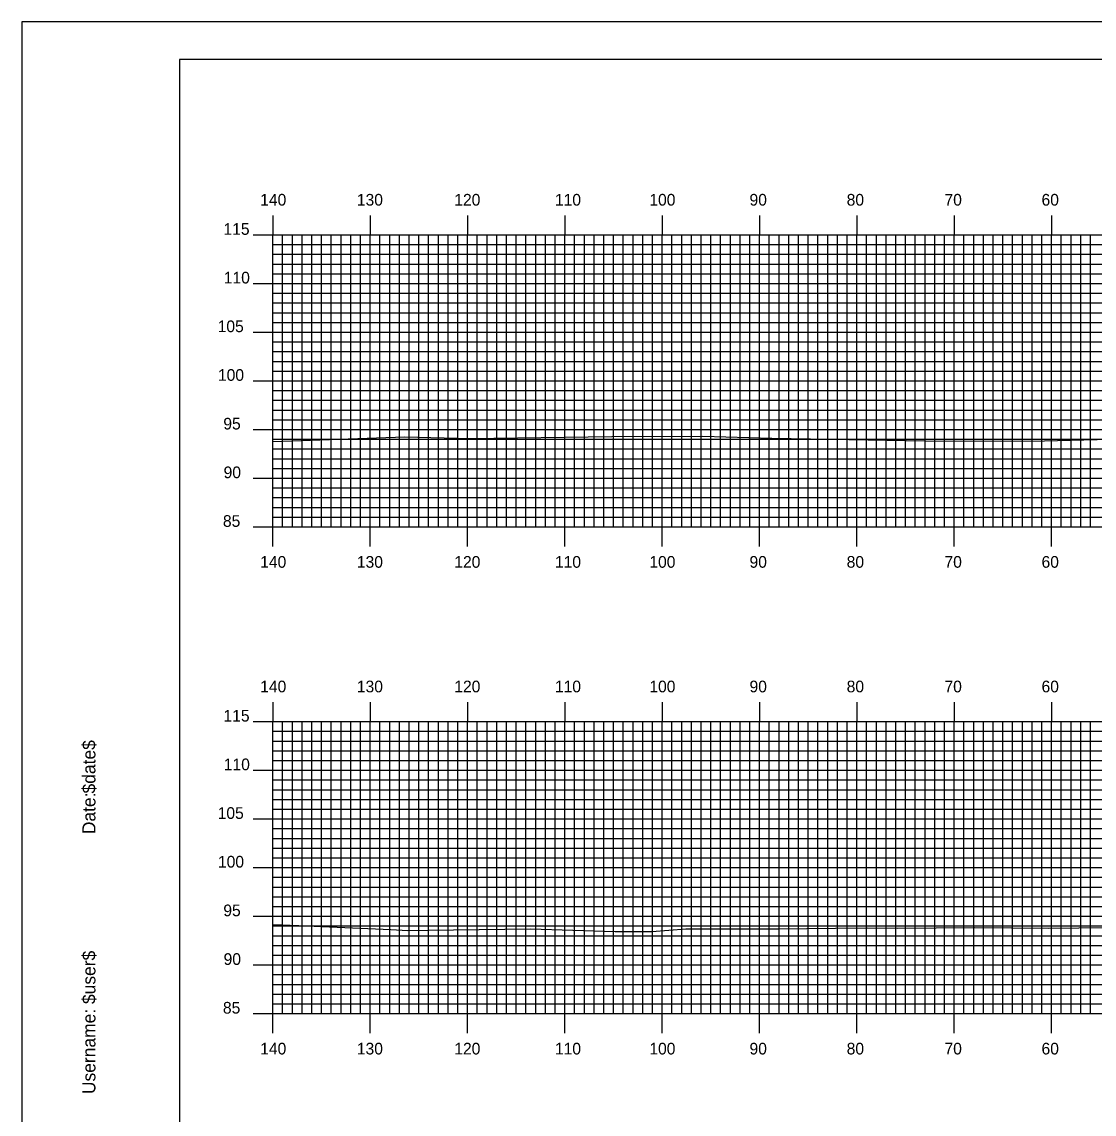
# Model space of a CAD drawing. Extents: x 1761004 to 1761347, y 442591 to 442811.
# Drawn here: x 1761003.9 to 1761114.1, y 442698.3 to 442810.5 of the extents above; entities that cross this region are included whole.
import ezdxf

# ---------------------------------------------------------------- set-up
doc = ezdxf.new("R2010")
doc.units = 0
for name, color, linetype in [('BORDER', 7, 'Continuous'), ('H_V ANNOTATION', 7, 'Continuous'), ('MAJOR', 7, 'Continuous'), ('MINOR', 7, 'Continuous'), ('PLOT BOUNDARY', 7, 'Continuous'), ('S_Roadway_Centerline', 7, 'Continuous')]:
    doc.layers.add(name, color=color, linetype=linetype)

msp = doc.modelspace()

# ---------------------------------------------------------------- linework, layer by layer
at = {"layer": 'BORDER'}
msp.add_lwpolyline([(1761020.13, 442596.67), (1761340.13, 442596.67), (1761340.13, 442806.67), (1761020.13, 442806.67)], close=True, dxfattribs=at)
at = {"layer": 'MAJOR'}
for p, q in [((1761029.73, 442790.67), (1761029.73, 442788.67)), ((1761039.73, 442790.67), (1761039.73, 442788.67)), ((1761049.73, 442790.67), (1761049.73, 442788.67)), ((1761059.73, 442790.67), (1761059.73, 442788.67)), ((1761069.73, 442790.67), (1761069.73, 442788.67)), ((1761079.73, 442790.67), (1761079.73, 442788.67)), ((1761089.73, 442790.67), (1761089.73, 442788.67)), ((1761099.73, 442790.67), (1761099.73, 442788.67)), ((1761109.73, 442790.67), (1761109.73, 442788.67)), ((1761027.72, 442788.67), (1761029.73, 442788.67)), ((1761029.73, 442788.67), (1761309.73, 442788.67)), ((1761029.73, 442758.67), (1761029.73, 442788.67)), ((1761029.73, 442758.67), (1761029.73, 442788.67)), ((1761029.73, 442788.67), (1761309.73, 442788.67)), ((1761039.73, 442758.67), (1761039.73, 442788.67)), ((1761049.73, 442758.67), (1761049.73, 442788.67)), ((1761059.73, 442758.67), (1761059.73, 442788.67)), ((1761069.73, 442758.67), (1761069.73, 442788.67)), ((1761079.73, 442758.67), (1761079.73, 442788.67)), ((1761089.73, 442758.67), (1761089.73, 442788.67)), ((1761099.73, 442758.67), (1761099.73, 442788.67)), ((1761109.73, 442758.67), (1761109.73, 442788.67)), ((1761027.72, 442783.67), (1761029.73, 442783.67)), ((1761029.73, 442783.67), (1761309.73, 442783.67)), ((1761027.72, 442778.67), (1761029.73, 442778.67)), ((1761029.73, 442778.67), (1761309.73, 442778.67)), ((1761027.72, 442773.67), (1761029.73, 442773.67)), ((1761029.73, 442773.67), (1761309.73, 442773.67)), ((1761027.72, 442768.67), (1761029.73, 442768.67)), ((1761029.73, 442768.67), (1761309.73, 442768.67)), ((1761027.72, 442763.67), (1761029.73, 442763.67)), ((1761029.73, 442763.67), (1761309.73, 442763.67)), ((1761027.72, 442758.67), (1761029.73, 442758.67)), ((1761029.73, 442758.67), (1761309.73, 442758.67)), ((1761029.73, 442758.67), (1761309.73, 442758.67)), ((1761029.73, 442756.66), (1761029.73, 442758.67)), ((1761039.73, 442756.66), (1761039.73, 442758.67)), ((1761049.73, 442756.66), (1761049.73, 442758.67)), ((1761059.73, 442756.66), (1761059.73, 442758.67)), ((1761069.73, 442756.66), (1761069.73, 442758.67)), ((1761079.73, 442756.66), (1761079.73, 442758.67)), ((1761089.73, 442756.66), (1761089.73, 442758.67)), ((1761099.73, 442756.66), (1761099.73, 442758.67)), ((1761109.73, 442756.66), (1761109.73, 442758.67)), ((1761029.73, 442740.67), (1761029.73, 442738.67)), ((1761039.73, 442740.67), (1761039.73, 442738.67)), ((1761049.73, 442740.67), (1761049.73, 442738.67)), ((1761059.73, 442740.67), (1761059.73, 442738.67)), ((1761069.73, 442740.67), (1761069.73, 442738.67)), ((1761079.73, 442740.67), (1761079.73, 442738.67)), ((1761089.73, 442740.67), (1761089.73, 442738.67)), ((1761099.73, 442740.67), (1761099.73, 442738.67)), ((1761109.73, 442740.67), (1761109.73, 442738.67)), ((1761027.72, 442738.67), (1761029.73, 442738.67)), ((1761029.73, 442738.67), (1761309.73, 442738.67)), ((1761029.73, 442708.67), (1761029.73, 442738.67)), ((1761029.73, 442708.67), (1761029.73, 442738.67)), ((1761029.73, 442738.67), (1761309.73, 442738.67)), ((1761039.73, 442708.67), (1761039.73, 442738.67)), ((1761049.73, 442708.67), (1761049.73, 442738.67)), ((1761059.73, 442708.67), (1761059.73, 442738.67)), ((1761069.73, 442708.67), (1761069.73, 442738.67)), ((1761079.73, 442708.67), (1761079.73, 442738.67)), ((1761089.73, 442708.67), (1761089.73, 442738.67)), ((1761099.73, 442708.67), (1761099.73, 442738.67)), ((1761109.73, 442708.67), (1761109.73, 442738.67)), ((1761027.72, 442733.67), (1761029.73, 442733.67)), ((1761029.73, 442733.67), (1761309.73, 442733.67)), ((1761027.72, 442728.67), (1761029.73, 442728.67)), ((1761029.73, 442728.67), (1761309.73, 442728.67)), ((1761027.72, 442723.67), (1761029.73, 442723.67)), ((1761029.73, 442723.67), (1761309.73, 442723.67)), ((1761027.72, 442718.67), (1761029.73, 442718.67)), ((1761029.73, 442718.67), (1761309.73, 442718.67)), ((1761027.72, 442713.67), (1761029.73, 442713.67)), ((1761029.73, 442713.67), (1761309.73, 442713.67)), ((1761027.72, 442708.67), (1761029.73, 442708.67)), ((1761029.73, 442708.67), (1761309.73, 442708.67)), ((1761029.73, 442708.67), (1761309.73, 442708.67)), ((1761029.73, 442706.66), (1761029.73, 442708.67)), ((1761039.73, 442706.66), (1761039.73, 442708.67)), ((1761049.73, 442706.66), (1761049.73, 442708.67)), ((1761059.73, 442706.66), (1761059.73, 442708.67)), ((1761069.73, 442706.66), (1761069.73, 442708.67)), ((1761079.73, 442706.66), (1761079.73, 442708.67)), ((1761089.73, 442706.66), (1761089.73, 442708.67)), ((1761099.73, 442706.66), (1761099.73, 442708.67)), ((1761109.73, 442706.66), (1761109.73, 442708.67))]:
    msp.add_line(p, q, dxfattribs=at)
at = {"layer": 'MINOR'}
for p, q in [((1761030.73, 442758.67), (1761030.73, 442788.67)), ((1761031.73, 442758.67), (1761031.73, 442788.67)), ((1761032.73, 442758.67), (1761032.73, 442788.67)), ((1761033.73, 442758.67), (1761033.73, 442788.67)), ((1761034.73, 442758.67), (1761034.73, 442788.67)), ((1761035.73, 442758.67), (1761035.73, 442788.67)), ((1761036.73, 442758.67), (1761036.73, 442788.67)), ((1761037.73, 442758.67), (1761037.73, 442788.67)), ((1761038.73, 442758.67), (1761038.73, 442788.67)), ((1761040.73, 442758.67), (1761040.73, 442788.67)), ((1761041.73, 442758.67), (1761041.73, 442788.67)), ((1761042.73, 442758.67), (1761042.73, 442788.67)), ((1761043.73, 442758.67), (1761043.73, 442788.67)), ((1761044.73, 442758.67), (1761044.73, 442788.67)), ((1761045.73, 442758.67), (1761045.73, 442788.67)), ((1761046.73, 442758.67), (1761046.73, 442788.67)), ((1761047.73, 442758.67), (1761047.73, 442788.67)), ((1761048.73, 442758.67), (1761048.73, 442788.67)), ((1761050.73, 442758.67), (1761050.73, 442788.67)), ((1761051.73, 442758.67), (1761051.73, 442788.67)), ((1761052.73, 442758.67), (1761052.73, 442788.67)), ((1761053.73, 442758.67), (1761053.73, 442788.67)), ((1761054.73, 442758.67), (1761054.73, 442788.67)), ((1761055.73, 442758.67), (1761055.73, 442788.67)), ((1761056.73, 442758.67), (1761056.73, 442788.67)), ((1761057.73, 442758.67), (1761057.73, 442788.67)), ((1761058.73, 442758.67), (1761058.73, 442788.67)), ((1761060.73, 442758.67), (1761060.73, 442788.67)), ((1761061.73, 442758.67), (1761061.73, 442788.67)), ((1761062.73, 442758.67), (1761062.73, 442788.67)), ((1761063.73, 442758.67), (1761063.73, 442788.67)), ((1761064.73, 442758.67), (1761064.73, 442788.67)), ((1761065.73, 442758.67), (1761065.73, 442788.67)), ((1761066.73, 442758.67), (1761066.73, 442788.67)), ((1761067.73, 442758.67), (1761067.73, 442788.67)), ((1761068.73, 442758.67), (1761068.73, 442788.67)), ((1761070.73, 442758.67), (1761070.73, 442788.67)), ((1761071.73, 442758.67), (1761071.73, 442788.67)), ((1761072.73, 442758.67), (1761072.73, 442788.67)), ((1761073.73, 442758.67), (1761073.73, 442788.67)), ((1761074.73, 442758.67), (1761074.73, 442788.67)), ((1761075.73, 442758.67), (1761075.73, 442788.67)), ((1761076.73, 442758.67), (1761076.73, 442788.67)), ((1761077.73, 442758.67), (1761077.73, 442788.67)), ((1761078.73, 442758.67), (1761078.73, 442788.67)), ((1761080.73, 442758.67), (1761080.73, 442788.67)), ((1761081.73, 442758.67), (1761081.73, 442788.67)), ((1761082.73, 442758.67), (1761082.73, 442788.67)), ((1761083.73, 442758.67), (1761083.73, 442788.67)), ((1761084.73, 442758.67), (1761084.73, 442788.67)), ((1761085.73, 442758.67), (1761085.73, 442788.67)), ((1761086.73, 442758.67), (1761086.73, 442788.67)), ((1761087.73, 442758.67), (1761087.73, 442788.67)), ((1761088.73, 442758.67), (1761088.73, 442788.67)), ((1761090.73, 442758.67), (1761090.73, 442788.67)), ((1761091.73, 442758.67), (1761091.73, 442788.67)), ((1761092.73, 442758.67), (1761092.73, 442788.67)), ((1761093.73, 442758.67), (1761093.73, 442788.67)), ((1761094.73, 442758.67), (1761094.73, 442788.67)), ((1761095.73, 442758.67), (1761095.73, 442788.67)), ((1761096.73, 442758.67), (1761096.73, 442788.67)), ((1761097.73, 442758.67), (1761097.73, 442788.67)), ((1761098.73, 442758.67), (1761098.73, 442788.67)), ((1761100.73, 442758.67), (1761100.73, 442788.67)), ((1761101.73, 442758.67), (1761101.73, 442788.67)), ((1761102.73, 442758.67), (1761102.73, 442788.67)), ((1761103.73, 442758.67), (1761103.73, 442788.67)), ((1761104.73, 442758.67), (1761104.73, 442788.67)), ((1761105.73, 442758.67), (1761105.73, 442788.67)), ((1761106.73, 442758.67), (1761106.73, 442788.67)), ((1761107.73, 442758.67), (1761107.73, 442788.67)), ((1761108.73, 442758.67), (1761108.73, 442788.67)), ((1761110.73, 442758.67), (1761110.73, 442788.67)), ((1761111.73, 442758.67), (1761111.73, 442788.67)), ((1761112.73, 442758.67), (1761112.73, 442788.67)), ((1761113.73, 442758.67), (1761113.73, 442788.67)), ((1761029.73, 442787.67), (1761309.73, 442787.67)), ((1761029.73, 442787.67), (1761031.73, 442787.67)), ((1761029.73, 442786.67), (1761309.73, 442786.67)), ((1761029.73, 442786.67), (1761031.73, 442786.67)), ((1761029.73, 442785.67), (1761309.73, 442785.67)), ((1761029.73, 442785.67), (1761031.73, 442785.67)), ((1761029.73, 442784.67), (1761309.73, 442784.67)), ((1761029.73, 442784.67), (1761031.73, 442784.67)), ((1761029.73, 442782.67), (1761309.73, 442782.67)), ((1761029.73, 442782.67), (1761031.73, 442782.67)), ((1761029.73, 442781.67), (1761309.73, 442781.67)), ((1761029.73, 442781.67), (1761031.73, 442781.67)), ((1761029.73, 442780.67), (1761309.73, 442780.67)), ((1761029.73, 442780.67), (1761031.73, 442780.67)), ((1761029.73, 442779.67), (1761309.73, 442779.67)), ((1761029.73, 442779.67), (1761031.73, 442779.67)), ((1761029.73, 442777.67), (1761309.73, 442777.67)), ((1761029.73, 442777.67), (1761031.73, 442777.67)), ((1761029.73, 442776.67), (1761309.73, 442776.67)), ((1761029.73, 442776.67), (1761031.73, 442776.67)), ((1761029.73, 442775.67), (1761309.73, 442775.67)), ((1761029.73, 442775.67), (1761031.73, 442775.67)), ((1761029.73, 442774.67), (1761309.73, 442774.67)), ((1761029.73, 442774.67), (1761031.73, 442774.67)), ((1761029.73, 442772.67), (1761309.73, 442772.67)), ((1761029.73, 442772.67), (1761031.73, 442772.67)), ((1761029.73, 442771.67), (1761309.73, 442771.67)), ((1761029.73, 442771.67), (1761031.73, 442771.67)), ((1761029.73, 442770.67), (1761309.73, 442770.67)), ((1761029.73, 442770.67), (1761031.73, 442770.67)), ((1761029.73, 442769.67), (1761309.73, 442769.67)), ((1761029.73, 442769.67), (1761031.73, 442769.67)), ((1761029.73, 442767.67), (1761309.73, 442767.67)), ((1761029.73, 442767.67), (1761031.73, 442767.67)), ((1761029.73, 442766.67), (1761309.73, 442766.67)), ((1761029.73, 442766.67), (1761031.73, 442766.67)), ((1761029.73, 442765.67), (1761309.73, 442765.67)), ((1761029.73, 442765.67), (1761031.73, 442765.67)), ((1761029.73, 442764.67), (1761309.73, 442764.67)), ((1761029.73, 442764.67), (1761031.73, 442764.67)), ((1761029.73, 442762.67), (1761309.73, 442762.67)), ((1761029.73, 442762.67), (1761031.73, 442762.67)), ((1761029.73, 442761.67), (1761309.73, 442761.67)), ((1761029.73, 442761.67), (1761031.73, 442761.67)), ((1761029.73, 442760.67), (1761309.73, 442760.67)), ((1761029.73, 442760.67), (1761031.73, 442760.67)), ((1761029.73, 442759.67), (1761309.73, 442759.67)), ((1761029.73, 442759.67), (1761031.73, 442759.67)), ((1761030.73, 442708.67), (1761030.73, 442738.67)), ((1761031.73, 442708.67), (1761031.73, 442738.67)), ((1761032.73, 442708.67), (1761032.73, 442738.67)), ((1761033.73, 442708.67), (1761033.73, 442738.67)), ((1761034.73, 442708.67), (1761034.73, 442738.67)), ((1761035.73, 442708.67), (1761035.73, 442738.67)), ((1761036.73, 442708.67), (1761036.73, 442738.67)), ((1761037.73, 442708.67), (1761037.73, 442738.67)), ((1761038.73, 442708.67), (1761038.73, 442738.67)), ((1761040.73, 442708.67), (1761040.73, 442738.67)), ((1761041.73, 442708.67), (1761041.73, 442738.67)), ((1761042.73, 442708.67), (1761042.73, 442738.67)), ((1761043.73, 442708.67), (1761043.73, 442738.67)), ((1761044.73, 442708.67), (1761044.73, 442738.67)), ((1761045.73, 442708.67), (1761045.73, 442738.67)), ((1761046.73, 442708.67), (1761046.73, 442738.67)), ((1761047.73, 442708.67), (1761047.73, 442738.67)), ((1761048.73, 442708.67), (1761048.73, 442738.67)), ((1761050.73, 442708.67), (1761050.73, 442738.67)), ((1761051.73, 442708.67), (1761051.73, 442738.67)), ((1761052.73, 442708.67), (1761052.73, 442738.67)), ((1761053.73, 442708.67), (1761053.73, 442738.67)), ((1761054.73, 442708.67), (1761054.73, 442738.67)), ((1761055.73, 442708.67), (1761055.73, 442738.67)), ((1761056.73, 442708.67), (1761056.73, 442738.67)), ((1761057.73, 442708.67), (1761057.73, 442738.67)), ((1761058.73, 442708.67), (1761058.73, 442738.67)), ((1761060.73, 442708.67), (1761060.73, 442738.67)), ((1761061.73, 442708.67), (1761061.73, 442738.67)), ((1761062.73, 442708.67), (1761062.73, 442738.67)), ((1761063.73, 442708.67), (1761063.73, 442738.67)), ((1761064.73, 442708.67), (1761064.73, 442738.67)), ((1761065.73, 442708.67), (1761065.73, 442738.67)), ((1761066.73, 442708.67), (1761066.73, 442738.67)), ((1761067.73, 442708.67), (1761067.73, 442738.67)), ((1761068.73, 442708.67), (1761068.73, 442738.67)), ((1761070.73, 442708.67), (1761070.73, 442738.67)), ((1761071.73, 442708.67), (1761071.73, 442738.67)), ((1761072.73, 442708.67), (1761072.73, 442738.67)), ((1761073.73, 442708.67), (1761073.73, 442738.67)), ((1761074.73, 442708.67), (1761074.73, 442738.67)), ((1761075.73, 442708.67), (1761075.73, 442738.67)), ((1761076.73, 442708.67), (1761076.73, 442738.67)), ((1761077.73, 442708.67), (1761077.73, 442738.67)), ((1761078.73, 442708.67), (1761078.73, 442738.67)), ((1761080.73, 442708.67), (1761080.73, 442738.67)), ((1761081.73, 442708.67), (1761081.73, 442738.67)), ((1761082.73, 442708.67), (1761082.73, 442738.67)), ((1761083.73, 442708.67), (1761083.73, 442738.67)), ((1761084.73, 442708.67), (1761084.73, 442738.67)), ((1761085.73, 442708.67), (1761085.73, 442738.67)), ((1761086.73, 442708.67), (1761086.73, 442738.67)), ((1761087.73, 442708.67), (1761087.73, 442738.67)), ((1761088.73, 442708.67), (1761088.73, 442738.67)), ((1761090.73, 442708.67), (1761090.73, 442738.67)), ((1761091.73, 442708.67), (1761091.73, 442738.67)), ((1761092.73, 442708.67), (1761092.73, 442738.67)), ((1761093.73, 442708.67), (1761093.73, 442738.67)), ((1761094.73, 442708.67), (1761094.73, 442738.67)), ((1761095.73, 442708.67), (1761095.73, 442738.67)), ((1761096.73, 442708.67), (1761096.73, 442738.67)), ((1761097.73, 442708.67), (1761097.73, 442738.67)), ((1761098.73, 442708.67), (1761098.73, 442738.67)), ((1761100.73, 442708.67), (1761100.73, 442738.67)), ((1761101.73, 442708.67), (1761101.73, 442738.67)), ((1761102.73, 442708.67), (1761102.73, 442738.67)), ((1761103.73, 442708.67), (1761103.73, 442738.67)), ((1761104.73, 442708.67), (1761104.73, 442738.67)), ((1761105.73, 442708.67), (1761105.73, 442738.67)), ((1761106.73, 442708.67), (1761106.73, 442738.67)), ((1761107.73, 442708.67), (1761107.73, 442738.67)), ((1761108.73, 442708.67), (1761108.73, 442738.67)), ((1761110.73, 442708.67), (1761110.73, 442738.67)), ((1761111.73, 442708.67), (1761111.73, 442738.67)), ((1761112.73, 442708.67), (1761112.73, 442738.67)), ((1761113.73, 442708.67), (1761113.73, 442738.67)), ((1761029.73, 442737.67), (1761309.73, 442737.67)), ((1761029.73, 442737.67), (1761031.73, 442737.67)), ((1761029.73, 442736.67), (1761309.73, 442736.67)), ((1761029.73, 442736.67), (1761031.73, 442736.67)), ((1761029.73, 442735.67), (1761309.73, 442735.67)), ((1761029.73, 442735.67), (1761031.73, 442735.67)), ((1761029.73, 442734.67), (1761309.73, 442734.67)), ((1761029.73, 442734.67), (1761031.73, 442734.67)), ((1761029.73, 442732.67), (1761309.73, 442732.67)), ((1761029.73, 442732.67), (1761031.73, 442732.67)), ((1761029.73, 442731.67), (1761309.73, 442731.67)), ((1761029.73, 442731.67), (1761031.73, 442731.67)), ((1761029.73, 442730.67), (1761309.73, 442730.67)), ((1761029.73, 442730.67), (1761031.73, 442730.67)), ((1761029.73, 442729.67), (1761309.73, 442729.67)), ((1761029.73, 442729.67), (1761031.73, 442729.67)), ((1761029.73, 442727.67), (1761309.73, 442727.67)), ((1761029.73, 442727.67), (1761031.73, 442727.67)), ((1761029.73, 442726.67), (1761309.73, 442726.67)), ((1761029.73, 442726.67), (1761031.73, 442726.67)), ((1761029.73, 442725.67), (1761309.73, 442725.67)), ((1761029.73, 442725.67), (1761031.73, 442725.67)), ((1761029.73, 442724.67), (1761309.73, 442724.67)), ((1761029.73, 442724.67), (1761031.73, 442724.67)), ((1761029.73, 442722.67), (1761309.73, 442722.67)), ((1761029.73, 442722.67), (1761031.73, 442722.67)), ((1761029.73, 442721.67), (1761309.73, 442721.67)), ((1761029.73, 442721.67), (1761031.73, 442721.67)), ((1761029.73, 442720.67), (1761309.73, 442720.67)), ((1761029.73, 442720.67), (1761031.73, 442720.67)), ((1761029.73, 442719.67), (1761309.73, 442719.67)), ((1761029.73, 442719.67), (1761031.73, 442719.67)), ((1761029.73, 442717.67), (1761309.73, 442717.67)), ((1761029.73, 442717.67), (1761031.73, 442717.67)), ((1761029.73, 442716.67), (1761309.73, 442716.67)), ((1761029.73, 442716.67), (1761031.73, 442716.67)), ((1761029.73, 442715.67), (1761309.73, 442715.67)), ((1761029.73, 442715.67), (1761031.73, 442715.67)), ((1761029.73, 442714.67), (1761309.73, 442714.67)), ((1761029.73, 442714.67), (1761031.73, 442714.67)), ((1761029.73, 442712.67), (1761309.73, 442712.67)), ((1761029.73, 442712.67), (1761031.73, 442712.67)), ((1761029.73, 442711.67), (1761309.73, 442711.67)), ((1761029.73, 442711.67), (1761031.73, 442711.67)), ((1761029.73, 442710.67), (1761309.73, 442710.67)), ((1761029.73, 442710.67), (1761031.73, 442710.67)), ((1761029.73, 442709.67), (1761309.73, 442709.67)), ((1761029.73, 442709.67), (1761031.73, 442709.67))]:
    msp.add_line(p, q, dxfattribs=at)
at = {"layer": 'PLOT BOUNDARY'}
msp.add_lwpolyline([(1761003.94, 442590.55), (1761343.94, 442590.55), (1761343.94, 442810.55), (1761003.94, 442810.55)], close=True, dxfattribs=at)
at = {"layer": 'S_Roadway_Centerline'}
for points in [[(1761029.73, 442767.45), (1761043.3, 442767.9), (1761050, 442767.76), (1761064.55, 442767.95), (1761073.9, 442767.99), (1761080.99, 442767.77), (1761086.94, 442767.69), (1761098.73, 442767.48), (1761109.02, 442767.52), (1761115.76, 442767.67)], [(1761029.73, 442717.81), (1761032.41, 442717.71), (1761041.85, 442717.3), (1761043.58, 442717.22), (1761045.66, 442717.24), (1761056.19, 442717.38), (1761064.89, 442717.11), (1761068.66, 442717.09), (1761072.15, 442717.37), (1761081.64, 442717.38), (1761087.53, 442717.46), (1761090.87, 442717.47), (1761093.9, 442717.44), (1761101.86, 442717.53), (1761109.37, 442717.44), (1761118.81, 442717.54)]]:
    msp.add_lwpolyline(points, dxfattribs=at)

# ---------------------------------------------------------------- texts
at = {"layer": 'BORDER'}
for s, p in [('$date$', (1761011.5, 442731.28)), ('Date:', (1761011.5, 442727.1)), ('$user$', (1761011.5, 442709.65)), ('Username:', (1761011.5, 442700.4))]:
    msp.add_text(s, height=1.339, rotation=90, dxfattribs=at).set_placement(p)
at = {"layer": 'H_V ANNOTATION'}
for s, p in [('140', (1761028.43, 442791.67)), ('130', (1761038.36, 442791.67)), ('120', (1761048.37, 442791.67)), ('110', (1761058.71, 442791.67)), ('100', (1761068.41, 442791.67)), ('90', (1761078.7, 442791.67)), ('80', (1761088.68, 442791.67)), ('70', (1761098.73, 442791.67)), ('60', (1761108.7, 442791.67)), ('115', (1761024.66, 442788.67)), ('110', (1761024.69, 442783.67)), ('105', (1761024.06, 442778.67)), ('100', (1761024.09, 442773.67)), ('95', (1761024.64, 442768.67)), ('90', (1761024.67, 442763.67)), ('85', (1761024.6, 442758.67)), ('140', (1761028.43, 442754.47)), ('130', (1761038.36, 442754.47)), ('120', (1761048.37, 442754.47)), ('110', (1761058.71, 442754.47)), ('100', (1761068.41, 442754.47)), ('90', (1761078.7, 442754.47)), ('80', (1761088.68, 442754.47)), ('70', (1761098.73, 442754.47)), ('60', (1761108.7, 442754.47)), ('140', (1761028.43, 442741.67)), ('130', (1761038.36, 442741.67)), ('120', (1761048.37, 442741.67)), ('110', (1761058.71, 442741.67)), ('100', (1761068.41, 442741.67)), ('90', (1761078.7, 442741.67)), ('80', (1761088.68, 442741.67)), ('70', (1761098.73, 442741.67)), ('60', (1761108.7, 442741.67)), ('115', (1761024.66, 442738.67)), ('110', (1761024.69, 442733.67)), ('105', (1761024.06, 442728.67)), ('100', (1761024.09, 442723.67)), ('95', (1761024.64, 442718.67)), ('90', (1761024.67, 442713.67)), ('85', (1761024.6, 442708.67)), ('140', (1761028.43, 442704.47)), ('130', (1761038.36, 442704.47)), ('120', (1761048.37, 442704.47)), ('110', (1761058.71, 442704.47)), ('100', (1761068.41, 442704.47)), ('90', (1761078.7, 442704.47)), ('80', (1761088.68, 442704.47)), ('70', (1761098.73, 442704.47)), ('60', (1761108.7, 442704.47))]:
    msp.add_text(s, height=1.2, dxfattribs=at).set_placement(p)
at = {"layer": 'MAJOR'}
for p in [(1761029.72, 442758.67), (1761029.72, 442708.67)]:
    msp.add_text('-', height=0.012, dxfattribs=at).set_placement(p)

doc.saveas('drawing.dxf')
